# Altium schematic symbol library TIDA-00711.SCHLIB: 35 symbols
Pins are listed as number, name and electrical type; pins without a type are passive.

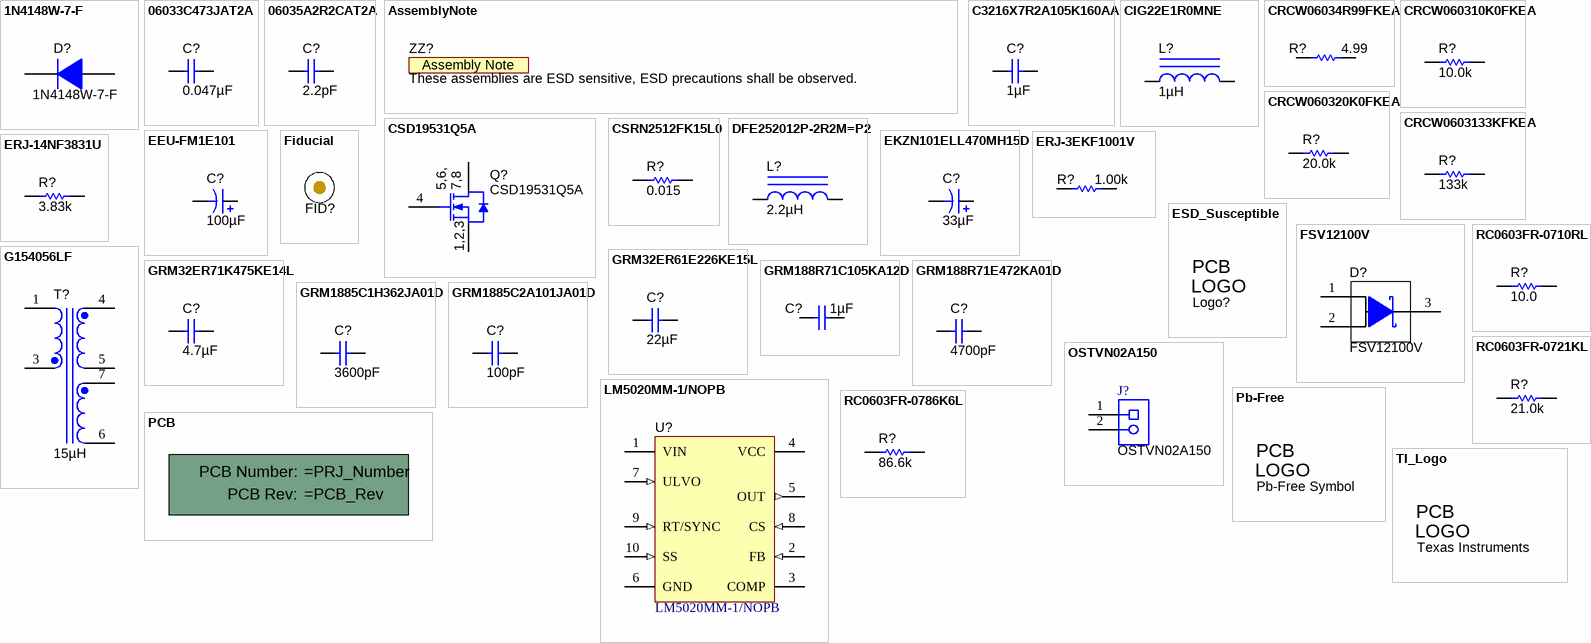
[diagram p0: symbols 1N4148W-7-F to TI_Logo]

## 1N4148W-7-F
designator D?
Diode, Ultrafast, 100 V, 0.15 A, SOD-123; Manufacturer: Diodes Inc.; U/M: EA; Vf_V: 1.25; Value: 100V; Value1: 0.15A; Value2: 1.25V; Io_A: 0.15; Vr_V: 100; TJmax_C: 150; SizeAreaWB_mm2: 13.095; SizeArea_mm2: 6.545; SizeX_mm: 3.85; SizeY_mm: 1.7; SizeZ_mm: 1.35; AEC Category: Q101
signal-integrity model Diode
simulation model 1N4148W
footprint SOD-123
pins: 1 K, 2 A

## 06033C473JAT2A
designator C?  ValueDisplayed: 0.047µF  (hidden comment: 06033C473JAT2A)
CAP, CERM, 0.047 µF, 25 V, +/- 5%, X7R, 0603; Manufacturer: AVX; Polarized: N; CompType: Capacitor; Value: 0.047uF; U/M: EA; Cap_F: 0.000000047; Tolerance_%: 5; ESR_ohm: 0.052; Value1: 0.052 ohm; VDC_V: 25; Value2: 25V; TaMin_C: -55; TaMax_C: 125; Cap_Case: 0603; SizeArea_mm2: 1.28; SizeAreaWB_mm2: 4.68; SizeX_mm: 1.6; SizeY_mm: 0.8; SizeZ_mm: 1; AEC Category: Q200
signal-integrity model Cap
simulation model Cap
footprint 0603
footprint 0603M
footprint 0603L
footprint 0603_HV
footprint 0603S
pins: 1, 2

## 06035A2R2CAT2A
designator C?  ValueDisplayed: 2.2pF  (hidden comment: 06035A2R2CAT2A)
CAP, CERM, 2.2 pF, 50 V, +/- 11%, C0G/NP0, 0603; Manufacturer: AVX; Polarized: N; CompType: Capacitor; Value: 2.2pF; U/M: EA; Cap_F: 0.0000000000022; Tolerance_%: 11; ESR_ohm: 1.033; Value1: 1.033 ohm; VDC_V: 50; Value2: 50V; TaMin_C: -55; TaMax_C: 125; Cap_Case: 0603; SizeArea_mm2: 1.28; SizeAreaWB_mm2: 4.68; SizeX_mm: 1.6; SizeY_mm: 0.8; SizeZ_mm: 1; AEC Category: Q200
signal-integrity model Cap
simulation model Cap
footprint 0603
footprint 0603M
footprint 0603L
footprint 0603_HV
footprint 0603S
pins: 1, 2

## AssemblyNote
designator ZZ?, comment These assemblies are ESD sensitive, ESD precautions shall be observed.  (no BOM)
SymbolCreator: codlsc; CompType: AssemblyNote
footprint AssemblyNote

## C3216X7R2A105K160AA
designator C?  ValueDisplayed: 1µF  (hidden comment: C3216X7R2A105K160AA)
CAP, CERM, 1 µF, 100 V, +/- 10%, X7R, 1206; Manufacturer: TDK; Polarized: N; CompType: Capacitor; Value: 1uF; U/M: EA; Cap_F: 0.000001; Tolerance_%: 10; ESR_ohm: 0.004575; Value1: 0.004575 ohm; VDC_V: 100; Value2: 100V; IRMS_A: 3.39639; TaMin_C: -55; TaMax_C: 125; Cap_Case: 1206_180; SizeArea_mm2: 5.12; SizeAreaWB_mm2: 10.92; SizeX_mm: 3.2; SizeY_mm: 1.6; SizeZ_mm: 1.8; AEC Category: Q200
signal-integrity model Cap
simulation model Cap
footprint 1206_180
footprint 1206_180M
footprint 1206_180L
pins: 1, 2

## CIG22E1R0MNE
designator L?  ValueDisplayed: 1µH  (hidden comment: CIG22E1R0MNE)
Inductor, Multilayer, 1 µH, 2.2 A, 0.048 ohm, SMD; Manufacturer: Samsung; Value: 1uH; Ind_H: 1.0E-6; Imax_A: 2.2; Irms: 2.9A @ 40C rise; Isat: 2.2A @ 30% inductance drop; DCR_ohm: 0.048; Value2: 2.2A; AEC Category: Q200
signal-integrity model Inductor
simulation model Inductor
footprint 1008
pins: 1, 2

## CRCW06034R99FKEA
designator R?  ValueDisplayed: 4.99  (hidden comment: CRCW06034R99FKEA)
RES, 4.99, 1%, 0.1 W, 0603; Manufacturer: Vishay-Dale; CompType: Resistor; Value: 4.99; Value_Code: 4R99; Tolerance_%: 1; Power_W: 0.1; Value2: 0.1W; VDC_V: 75; TempCo: 100 ppm/C; SizeArea_mm2: 1.28; SizeX_mm: 1.6; SizeY_mm: 0.8; EIA_Code: E96; U/M: EA; AEC Category: Q200
signal-integrity model Resistor
simulation model Resistor
footprint 0603
footprint 0603M
footprint 0603L
footprint 0603_HV
footprint 0603S
pins: 1, 2

## CRCW060310K0FKEA
designator R?  ValueDisplayed: 10.0k  (hidden comment: CRCW060310K0FKEA)
RES, 10.0 k, 1%, 0.1 W, 0603; Manufacturer: Vishay-Dale; CompType: Resistor; Value: 10.0k; Res_ohm: 10000; Value_Code: 10k0; Tolerance_%: 1; Power_W: 0.1; Value2: 0.1W; VDC_V: 75; TempCo: 100 ppm/C; SizeArea_mm2: 1.28; SizeX_mm: 1.6; SizeY_mm: 0.8; EIA_Code: E96; U/M: EA; AEC Category: Q200
signal-integrity model Resistor
simulation model Resistor
footprint 0603
footprint 0603M
footprint 0603L
footprint 0603_HV
footprint 0603S
pins: 1, 2

## CRCW060320K0FKEA
designator R?  ValueDisplayed: 20.0k  (hidden comment: CRCW060320K0FKEA)
RES, 20.0 k, 1%, 0.1 W, 0603; Manufacturer: Vishay-Dale; CompType: Resistor; Value: 20.0k; Res_ohm: 20000; Value_Code: 20k0; Tolerance_%: 1; Power_W: 0.1; Value2: 0.1W; VDC_V: 75; TempCo: 100 ppm/C; SizeArea_mm2: 1.28; SizeX_mm: 1.6; SizeY_mm: 0.8; EIA_Code: E96; U/M: EA; AEC Category: Q200
signal-integrity model Resistor
simulation model Resistor
footprint 0603
footprint 0603M
footprint 0603L
footprint 0603_HV
footprint 0603S
pins: 1, 2

## CRCW0603133KFKEA
designator R?  ValueDisplayed: 133k  (hidden comment: CRCW0603133KFKEA)
RES, 133 k, 1%, 0.1 W, 0603; Manufacturer: Vishay-Dale; CompType: Resistor; Value: 133k; Res_ohm: 133000; Tolerance_%: 1; Power_W: 0.1; Value2: 0.1W; VDC_V: 75; TempCo: 100 ppm/C; SizeArea_mm2: 1.28; SizeX_mm: 1.6; SizeY_mm: 0.8; EIA_Code: E96; U/M: EA; AEC Category: Q200
signal-integrity model Resistor
simulation model Resistor
footprint 0603
footprint 0603M
footprint 0603L
footprint 0603_HV
footprint 0603S
pins: 1, 2

## CSD19531Q5A
designator Q?
MOSFET, N-CH, 100 V, 16 A, SON 5x6mm; Manufacturer: Texas Instruments; Alternate Manufacturer: None; U/M: EA; ChType: N; Value: 100V; VdsMax_V: 100; Value1: ? ohm; Value2: 36 nC; QgTyp_nC: 36; Vgs_V: 20; IdsMax_A: 16; SizeAreaWB_mm2: 55.2; SizeArea_mm2: 29.4; SizeX_mm: 6; SizeY_mm: 4.9; SizeZ_mm: 1; AEC Category: Q101
footprint TRANS_NexFET_Q5A
pins: 1 S, 2 S, 3 S, 4 G, 5 D, 6 D, 7 D, 8 D, 9 D

## CSRN2512FK15L0
designator R?  ValueDisplayed: 0.015  (hidden comment: CSRN2512FK15L0)
RES, 0.015, 1%, 2 W, 2512; Manufacturer: Stackpole Electronics Inc; CompType: Resistor; Value: 0.015; Value_Code: R015; Tolerance_%: 1; Power_W: 2; Value2: 2W; TempCo: 200 ppm/C; SizeArea_mm2: 20.16; SizeX_mm: 6.3; SizeY_mm: 3.2; SizeZ_mm: 0.71; EIA_Code: E96; U/M: EA; AEC Category: Q200
signal-integrity model Resistor
simulation model Resistor
footprint 2512
footprint 2512M
footprint 2512L
pins: 1, 2

## DFE252012P-2R2M=P2
designator L?, comment ValueDisplayed: 2.2µH  (hidden comment: RLB0912-2R2ML)
Inductor, Shielded, 2.2 µH, 2.6 A, 0.07 ohm, SMD; Manufacturer: MuRata Toko; Value: 2.2uH; Ind_H: 2.2E-6; Imax_A: 2.6; Irms: 2.6A @ 40C rise; Isat: 3.3A @ 30% inductance drop; DCR_ohm: 0.07; Value2: 2.6A; AEC Category: Q200
signal-integrity model Inductor
simulation model Inductor
footprint DFE252012P
footprint RLB9012 (TH, 2-Leads, Dia 9mm, Pin Spacing 5mm)
pins: 1, 2

## EEU-FM1E101
designator C?  ValueDisplayed: 100µF  (hidden comment: EEU-FM1E101)
CAP, AL, 100 µF, 25 V, +/- 20%, 0.13 ohm, TH; Manufacturer: Panasonic; Polarized: Y; CompType: Capacitor; Value: 100uF; U/M: EA; Cap_F: 0.0001; Tolerance_%: 20; VDC_V: 25; Value2: 25V; ESR_ohm: 0.13; IRMS_A: 0.455; TaMin_C: -40; TaMax_C: 105; Cap_Case: 6.3x11.2; AEC Category: Q200; AEC Qualified: N
signal-integrity model Cap
simulation model Cap
footprint FM_630x1120
pins: 1 +, 2 -

## EKZN101ELL470MH15D
designator C?, comment ValueDisplayed: 33µF  (hidden comment: UPM2A330MPD1TD)
CAP, AL, 47 µF, 100 V, +/- 20%, 0.14 ohm, TH; Manufacturer: Nichicon; Polarized: Y; CompType: Capacitor; Value: 47uF; U/M: EA; Cap_F: 0.000047; Tolerance_%: 20; VDC_V: 100; Value2: 100V; ESR_ohm: 0.14; IRMS_A: 0.78; TaMin_C: -40; TaMax_C: 105; Cap_Case: 8x15mm; AEC Category: Q200; AEC Qualified: N
signal-integrity model Cap
simulation model Cap
footprint KZN_800x1500
pins: 1 +, 2 -

## ERJ-3EKF1001V
designator R?  ValueDisplayed: 1.00k  (hidden comment: ERJ-3EKF1001V)
RES, 1.00 k, 1%, 0.1 W, 0603; Manufacturer: Panasonic; CompType: Resistor; Value: 1.00k; Res_ohm: 1000; Value_Code: 1k00; Tolerance_%: 1; Power_W: 0.1; Value2: 0.1W; VDC_V: 75; TempCo: 100 ppm/C; SizeArea_mm2: 1.28; SizeX_mm: 1.6; SizeY_mm: 0.8; EIA_Code: E96; U/M: EA; AEC Category: Q200
signal-integrity model Resistor
simulation model Resistor
footprint 0603
footprint 0603M
footprint 0603L
footprint 0603_HV
footprint 0603S
pins: 1, 2

## ERJ-14NF3831U
designator R?  ValueDisplayed: 3.83k  (hidden comment: ERJ-14NF3831U)
RES, 3.83 k, 1%, 0.5 W, 1210; Manufacturer: Panasonic; CompType: Resistor; Value: 3.83k; Res_ohm: 3830; Value_Code: 3k83; Tolerance_%: 1; Power_W: 0.5; Value2: 0.5W; VDC_V: 200; TempCo: 100 ppm/C; SizeArea_mm2: 8; SizeAreaWB_mm2: 14.7; SizeX_mm: 3.2; SizeY_mm: 2.5; SizeZ_mm: 1.35; EIA_Code: E96; U/M: EA; AEC Category: Q200
signal-integrity model Resistor
simulation model Resistor
footprint 1210M
footprint 1210L
footprint 1210
pins: 1, 2

## ESD_Susceptible
designator Logo?, comment ESD Susceptible  (value not drawn)  (no BOM)
ESD Susceptible Symbol; SymbolCreator: a0412235
footprint ESD_Overlay_Large
footprint ESD_Overlay_Medium
footprint ESD_Overlay_Small

## Fiducial
designator FID?  (value not drawn)
Fiducial mark.  There is nothing to buy or mount.; SymbolCreator: codlsc
footprint Fiducial10-30
footprint Fiducial10-20
footprint Fiducial15-30
footprint Fiducial20-40
footprint Fiducial6.4-20

## FSV12100V
designator D?
Diode, Schottky, 100 V, 12 A, AEC-Q101, TO-277A; Manufacturer: Fairchild Semiconductor; U/M: EA; Vf_V: 0.67; Value: 100V; Value1: 12A; Value2: 0.67V; Io_A: 12; Vr_V: 100; TJmax_C: 150; SizeAreaWB_mm2: 56.1; SizeArea_mm2: 29.9; SizeX_mm: 4.6; SizeY_mm: 6.5; SizeZ_mm: 1.2; AEC Category: Q101; AEC Qualified: Y
signal-integrity model Diode
footprint TO-277A
pins: 1 A, 2 A, 3 K

## G154056LF
designator T?  ValueDisplayed: 15µH  (hidden comment: G154056LF)
Transformer, 765 uH, SMT; Manufacturer: GCI Technologies; SymbolCreator: Altium; Value: 765uH; Lp: 15uH; DCR_ohm: 1; LeakageL: 8
footprint WE_750343306_CUS (TRANSFORMER, TH, 14-PIN)
footprint WE_750343373 (TRANSFOERMER, TH, 10-PIN)
footprint WE_750343373 (TRANSFOERMER, TH, 10-PIN)
footprint WE_750343373 (TRANSFOERMER, TH, 10-PIN)
pins: 1, 3, 4, 5, 6, 7

## GRM32ER61E226KE15L
designator C?  ValueDisplayed: 22µF  (hidden comment: GRM32ER61E226KE15L)
CAP, CERM, 22 µF, 25 V, +/- 10%, X5R, 1210; Manufacturer: MuRata; Polarized: N; CompType: Capacitor; Value: 22uF; U/M: EA; Cap_F: 0.000022; Tolerance_%: 10; ESR_ohm: 0.002; Value1: 0.002 ohm; VDC_V: 25; Value2: 25V; IRMS_A: 3.67; TaMin_C: -55; TaMax_C: 85; Cap_Case: 1210; SizeArea_mm2: 8; SizeAreaWB_mm2: 14.7; SizeX_mm: 3.2; SizeY_mm: 2.5; SizeZ_mm: 2.7; AEC Category: Q200
signal-integrity model Cap
simulation model Cap
footprint 1210_270
footprint 1210_270M
footprint 1210_270L
pins: 1, 2

## GRM32ER71K475KE14L
designator C?  ValueDisplayed: 4.7µF  (hidden comment: GRM32ER71K475KE14L)
CAP, CERM, 4.7 µF, 80 V, +/- 10%, X7R, 1210; Manufacturer: MuRata; Polarized: N; CompType: Capacitor; Value: 4.7uF; U/M: EA; Cap_F: 0.0000047; Tolerance_%: 10; Value1: Unknown; VDC_V: 80; Value2: 80V; TaMin_C: -55; TaMax_C: 125; Cap_Case: 1210; SizeArea_mm2: 8; SizeAreaWB_mm2: 14.7; SizeX_mm: 3.2; SizeY_mm: 2.5; SizeZ_mm: 2.7; AEC Category: Q200
signal-integrity model Cap
simulation model Cap
footprint 1210_270
footprint 1210_270M
footprint 1210_270L
pins: 1, 2

## GRM188R71C105KA12D
designator C?  ValueDisplayed: 1µF  (hidden comment: GRM188R71C105KA12D)
CAP, CERM, 1 µF, 16 V, +/- 10%, X7R, 0603; Manufacturer: MuRata; Polarized: N; CompType: Capacitor; Value: 1uF; U/M: EA; Cap_F: 0.000001; Tolerance_%: 10; ESR_ohm: 0.011; Value1: 0.011 ohm; VDC_V: 16; Value2: 16V; TaMin_C: -55; TaMax_C: 125; Cap_Case: 0603; SizeArea_mm2: 1.28; SizeAreaWB_mm2: 4.68; SizeX_mm: 1.6; SizeY_mm: 0.8; SizeZ_mm: 1; AEC Category: Q200
signal-integrity model Cap
simulation model Cap
footprint 0603
footprint 0603M
footprint 0603L
footprint 0603_HV
footprint 0603S
pins: 1, 2

## GRM188R71E472KA01D
designator C?  ValueDisplayed: 4700pF  (hidden comment: GRM188R71E472KA01D)
CAP, CERM, 4700 pF, 25 V, +/- 10%, X7R, 0603; Manufacturer: MuRata; Polarized: N; CompType: Capacitor; Value: 4700pF; U/M: EA; Cap_F: 0.0000000047; Tolerance_%: 10; Value1: Unknown; VDC_V: 25; Value2: 25V; TaMin_C: -55; TaMax_C: 125; Cap_Case: 0603; SizeArea_mm2: 1.28; SizeAreaWB_mm2: 4.68; SizeX_mm: 1.6; SizeY_mm: 0.8; SizeZ_mm: 1; AEC Category: Q200
signal-integrity model Cap
simulation model Cap
footprint 0603
footprint 0603M
footprint 0603L
footprint 0603_HV
footprint 0603S
pins: 1, 2

## GRM1885C1H362JA01D
designator C?  ValueDisplayed: 3600pF  (hidden comment: GRM1885C1H362JA01D)
CAP, CERM, 3600 pF, 50 V, +/- 5%, C0G/NP0, 0603; Manufacturer: MuRata; Polarized: N; CompType: Capacitor; Value: 3600pF; U/M: EA; Cap_F: 0.0000000036; Tolerance_%: 5; Value1: Unknown; VDC_V: 50; Value2: 50V; TaMin_C: -55; TaMax_C: 125; Cap_Case: 0603; SizeArea_mm2: 1.28; SizeAreaWB_mm2: 4.68; SizeX_mm: 1.6; SizeY_mm: 0.8; SizeZ_mm: 1; AEC Category: Q200
signal-integrity model Cap
simulation model Cap
footprint 0603
footprint 0603M
footprint 0603L
footprint 0603_HV
footprint 0603S
pins: 1, 2

## GRM1885C2A101JA01D
designator C?  ValueDisplayed: 100pF  (hidden comment: GRM1885C2A101JA01D)
CAP, CERM, 100 pF, 100 V, +/- 5%, C0G/NP0, 0603; Manufacturer: MuRata; Polarized: N; CompType: Capacitor; Value: 100pF; U/M: EA; Cap_F: 0.0000000001; Tolerance_%: 5; Value1: Unknown; VDC_V: 100; Value2: 100V; TaMin_C: -55; TaMax_C: 125; Cap_Case: 0603; SizeArea_mm2: 1.28; SizeAreaWB_mm2: 4.68; SizeX_mm: 1.6; SizeY_mm: 0.8; SizeZ_mm: 1; AEC Category: Q200
signal-integrity model Cap
simulation model Cap
footprint 0603
footprint 0603M
footprint 0603L
footprint 0603_HV
footprint 0603S
pins: 1, 2

## LM5020MM-1/NOPB
designator U?
100V Current Mode PWM Controller, 10-pin MSOP, Pb-Free; Manufacturer: Texas Instruments; PackageTopMarking: ZXTT*SBLB; PowerWise: Y; CompType: Switcher
footprint MUB10A_N (TSSOP, 10-Leads, Body 3x3mm, Pitch 0.5mm, IPC Medium Density)
footprint MUB10A_L (TSSOP, 10-Leads, Body 3x3mm, Pitch 0.5mm, IPC High Density)
footprint MUB10A_M (TSSOP, 10-Leads, Body 3x3mm, Pitch 0.5mm, IPC Low Density)
pins: 1 VIN (power), 2 FB (in), 3 COMP, 4 VCC (power), 5 OUT (out), 6 GND (power), 7 ULVO (in), 8 CS (in), 9 RT/SYNC (in), 10 SS (in)

## OSTVN02A150
designator J?
Terminal Block, 2.54mm, 2x1, Brass, TH; Manufacturer: On-Shore Technology; SymbolCreator: a0412235
footprint On-Shore_OSTVN02A150
pins: 1, 2

## Pb-Free
designator Logo?, comment Pb-Free Symbol  (no BOM)
SymbolCreator: a0412235
footprint Pb-Free_Overlay_Medium
footprint Pb-Free_Overlay_Small

## PCB
designator !PCB?, comment Printed Circuit Board  (value not drawn)  (mechanical)
Manufacturer: Any; SymbolCreator: a0412235; CompType: PCB
1 alternate drawing of the same symbol

## RC0603FR-0710RL
designator R?  ValueDisplayed: 10.0  (hidden comment: RC0603FR-0710RL)
RES, 10.0, 1%, 0.1 W, 0603; Manufacturer: Yageo America; CompType: Resistor; Value: 10.0; Res_ohm: 10; Value_Code: 10R0; Tolerance_%: 1; Power_W: 0.1; Value2: 0.1W; VDC_V: 150; TempCo: 200 ppm/C; SizeArea_mm2: 1.28; SizeX_mm: 1.6; SizeY_mm: 0.8; EIA_Code: E96; U/M: EA; AEC Category: Q200
signal-integrity model Resistor
simulation model Resistor
footprint 0603
footprint 0603M
footprint 0603L
footprint 0603_HV
footprint 0603S
pins: 1, 2

## RC0603FR-0721KL
designator R?  ValueDisplayed: 21.0k  (hidden comment: RC0603FR-0721KL)
RES, 21.0 k, 1%, 0.1 W, 0603; Manufacturer: Yageo America; CompType: Resistor; Value: 21.0k; Res_ohm: 21000; Value_Code: 21k0; Tolerance_%: 1; Power_W: 0.1; Value2: 0.1W; VDC_V: 150; TempCo: 200 ppm/C; SizeArea_mm2: 1.28; SizeX_mm: 1.6; SizeY_mm: 0.8; EIA_Code: E96; U/M: EA; AEC Category: Q200
signal-integrity model Resistor
simulation model Resistor
footprint 0603
footprint 0603M
footprint 0603L
footprint 0603_HV
footprint 0603S
pins: 1, 2

## RC0603FR-0786K6L
designator R?  ValueDisplayed: 86.6k  (hidden comment: RC0603FR-0786K6L)
RES, 86.6 k, 1%, 0.1 W, 0603; Manufacturer: Yageo America; CompType: Resistor; Value: 86.6k; Res_ohm: 86600; Value_Code: 86k6; Tolerance_%: 1; Power_W: 0.1; Value2: 0.1W; VDC_V: 150; TempCo: 200 ppm/C; SizeArea_mm2: 1.28; SizeX_mm: 1.6; SizeY_mm: 0.8; EIA_Code: E96; U/M: EA; AEC Category: Q200
signal-integrity model Resistor
simulation model Resistor
footprint 0603
footprint 0603M
footprint 0603L
footprint 0603_HV
footprint 0603S
pins: 1, 2

## TI_Logo
designator Logo?, comment Texas Instruments  (no BOM)
Texas Instrument Corporate Signature; SymbolCreator: codlsc
footprint TI_Stacked_SolderMask_Medium
footprint TI_Stacked_SolderMask_Small
footprint TI_Stacked_Overlay_Medium
footprint TI_Stacked_Overlay_Small
footprint TI_Horizontal_SolderMask_Medium
footprint TI_Horizontal_SolderMask_Small
footprint TI_Horizontal_Overlay_Medium
footprint TI_Horizontal_Overlay_Small
footprint TI_Symbol_SolderMask_Small
footprint TI_Symbol_Overlay_Medium
footprint TI_Symbol_Overlay_Small
footprint TI_Symbol_SolderMask_Medium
